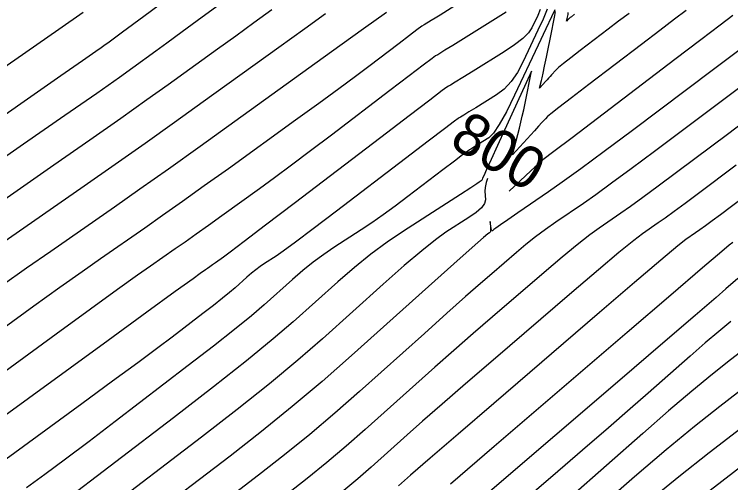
# Model space of a CAD drawing. Extents: x 2079879 to 2092887, y 778083 to 784051.
# Drawn here: x 2083989.89 to 2084037.6, y 780813.21 to 780844.44 of the extents above; entities that cross this region are included whole.
import ezdxf

# ---------------------------------------------------------------- set-up
doc = ezdxf.new("R2010")
doc.units = 0
doc.layers.add('DT_X_Contour_Major', color=7, linetype='Continuous')
doc.layers.add('DT_X_Contour_Minor', color=7, linetype='Continuous')

msp = doc.modelspace()

# ---------------------------------------------------------------- linework, layer by layer
at = {"layer": 'DT_X_Contour_Major'}
for points in [[(2084010.72, 780850.406), (2084010.313, 780850.113), (2084008.721, 780848.939), (2084004.016, 780845.443), (2084002.4, 780844.244), (2084001.079, 780843.267), (2084000.055, 780842.513), (2083999.326, 780841.983), (2083997.776, 780840.865), (2083996.886, 780840.232), (2083995.377, 780839.173), (2083993.25, 780837.687), (2083990.504, 780835.775), (2083982.357, 780830.105)], [(2084022.658, 780844.588), (2084021.945, 780844.143), (2084019.804, 780842.811), (2084019.095, 780842.37), (2084018.573, 780842.046), (2084018.238, 780841.839), (2084018.089, 780841.749), (2084017.943, 780841.664), (2084017.713, 780841.497), (2084017.13, 780841.059), (2084016.196, 780840.35), (2084014.911, 780839.37), (2084011.013, 780836.395), (2084009.617, 780835.335), (2084008.352, 780834.384), (2084007.218, 780833.544), (2084006.216, 780832.813), (2084003.717, 780831.011), (2084002.82, 780830.366), (2084002.003, 780829.782), (2084001.266, 780829.26), (2084000.608, 780828.799), (2083998.96, 780827.652), (2083998.103, 780827.046), (2083996.77, 780826.088), (2083994.96, 780824.777), (2083992.674, 780823.114), (2083985.941, 780818.21)], [(2084037.749, 780844.363), (2084036.898, 780843.714), (2084035.614, 780842.736), (2084033.895, 780841.427), (2084028.733, 780837.497), (2084027.039, 780836.207), (2084025.828, 780835.286), (2084025.102, 780834.733), (2084024.859, 780834.548), (2084024.856, 780834.545), (2084024.854, 780834.542), (2084024.849, 780834.537), (2084024.842, 780834.529), (2084024.832, 780834.518), (2084024.803, 780834.486), (2084024.792, 780834.475), (2084024.784, 780834.466), (2084024.778, 780834.458), (2084024.773, 780834.454), (2084024.764, 780834.443), (2084024.709, 780834.391), (2084024.552, 780834.245), (2084024.292, 780834.003), (2084023.931, 780833.667), (2084022.849, 780832.66)], [(2084021.416, 780833.499), (2084021.319, 780833.219), (2084021.246, 780832.901), (2084021.232, 780832.649), (2084021.271, 780832.063), (2084021.213, 780831.824), (2084021.008, 780831.549), (2084020.657, 780831.236), (2084020.16, 780830.887), (2084018.638, 780829.906), (2084017.949, 780829.413), (2084017.023, 780828.673), (2084015.86, 780827.683), (2084014.46, 780826.446), (2084010.41, 780822.814), (2084008.768, 780821.382), (2084006.878, 780819.811), (2084004.742, 780818.101), (2084002.358, 780816.251), (2083995.671, 780811.132)], [(2084038.477, 780832.249), (2084036.921, 780831.081), (2084036.381, 780830.676), (2084035.925, 780830.34), (2084035.555, 780830.072), (2084035.271, 780829.872), (2084034.625, 780829.43), (2084034.084, 780829.002), (2084032.942, 780828.046), (2084031.201, 780826.565), (2084028.861, 780824.558), (2084021.819, 780818.503), (2084019.443, 780816.457), (2084017.593, 780814.859), (2084016.272, 780813.711), (2084015.478, 780813.011)], [(2084041.095, 780821.553), (2084036.888, 780818.301), (2084035.204, 780816.965), (2084033.305, 780815.397), (2084031.193, 780813.597), (2084028.867, 780811.564), (2084022.378, 780805.834), (2084020.224, 780803.935), (2084018.628, 780802.537), (2084017.589, 780801.64), (2084017.108, 780801.244), (2084016.571, 780800.854), (2084016.195, 780800.587), (2084015.472, 780800.077), (2084014.401, 780799.326), (2084012.982, 780798.332), (2084008.735, 780795.359), (2084007.243, 780794.315), (2084005.952, 780793.414), (2084004.863, 780792.656), (2084003.975, 780792.04), (2084002.509, 780791.027)]]:
    msp.add_lwpolyline(points, dxfattribs=at)
at = {"layer": 'DT_X_Contour_Minor'}
for points in [[(2084000.474, 780845.757), (2083998.512, 780844.299), (2083997.089, 780843.244), (2083996.206, 780842.591), (2083995.863, 780842.34), (2083995.666, 780842.208), (2083995.319, 780841.967), (2083994.423, 780841.343), (2083992.98, 780840.335), (2083990.99, 780838.944), (2083984.951, 780834.725)], [(2084019.237, 780845.009), (2084018.248, 780844.394), (2084017.915, 780844.188), (2084017.658, 780844.029), (2084017.476, 780843.917), (2084017.37, 780843.854), (2084017.188, 780843.748), (2084017.033, 780843.641), (2084016.704, 780843.398), (2084016.202, 780843.02), (2084015.527, 780842.506), (2084013.494, 780840.955), (2084012.617, 780840.294), (2084011.512, 780839.478), (2084010.179, 780838.504), (2084008.618, 780837.374), (2084004.149, 780834.15), (2084002.545, 780832.996), (2084001.083, 780831.952), (2083999.764, 780831.018), (2083998.587, 780830.194), (2083995.639, 780828.143), (2083994.408, 780827.278), (2083992.927, 780826.221), (2083991.194, 780824.973), (2083989.211, 780823.533)], [(2084007.035, 780844.744), (2084005.848, 780843.873), (2084004.643, 780842.994), (2084003.419, 780842.107), (2084000.128, 780839.733), (2083998.727, 780838.731), (2083996.993, 780837.505), (2083994.926, 780836.054), (2083992.525, 780834.38), (2083985.678, 780829.615)], [(2083994.476, 780844.558), (2083992.856, 780843.439), (2083990.651, 780841.906), (2083987.861, 780839.959)], [(2084024.912, 780844.754), (2084024.757, 780844.37), (2084024.364, 780843.537), (2084024.138, 780843.204), (2084023.754, 780842.827), (2084023.214, 780842.408), (2084022.516, 780841.946), (2084020.444, 780840.658), (2084019.76, 780840.232), (2084019.259, 780839.921), (2084018.942, 780839.725), (2084018.809, 780839.644), (2084018.699, 780839.58), (2084018.393, 780839.353), (2084017.557, 780838.72), (2084016.191, 780837.68), (2084014.295, 780836.234), (2084008.532, 780831.836), (2084006.616, 780830.375), (2084005.191, 780829.291), (2084004.257, 780828.583), (2084003.814, 780828.252), (2084003.286, 780827.871), (2084003.096, 780827.735), (2084002.923, 780827.612), (2084002.767, 780827.501), (2084002.628, 780827.404), (2084002.28, 780827.161), (2084001.798, 780826.814), (2084000.614, 780825.954), (2083998.726, 780824.581), (2083996.136, 780822.695), (2083988.293, 780816.982)], [(2084025.378, 780844.774), (2084025.107, 780844.117), (2084024.771, 780843.376), (2084023.787, 780841.291), (2084023.4, 780840.566), (2084022.974, 780839.956), (2084022.511, 780839.461), (2084022.01, 780839.08), (2084020.623, 780838.217), (2084020.165, 780837.932), (2084019.829, 780837.724), (2084019.617, 780837.593), (2084019.528, 780837.538), (2084019.454, 780837.496), (2084019.215, 780837.317), (2084018.55, 780836.814), (2084017.462, 780835.985), (2084015.949, 780834.831), (2084011.349, 780831.32), (2084009.803, 780830.145), (2084008.617, 780829.252), (2084007.79, 780828.643), (2084007.323, 780828.316), (2084006.556, 780827.821), (2084006.267, 780827.625), (2084005.975, 780827.409), (2084005.681, 780827.172), (2084005.384, 780826.915), (2084004.59, 780826.203), (2084004.233, 780825.896), (2084003.758, 780825.507), (2084003.164, 780825.038), (2084002.452, 780824.488), (2084000.397, 780822.915), (2083999.442, 780822.194), (2083998.121, 780821.214), (2083996.433, 780819.974), (2083994.377, 780818.473), (2083988.407, 780814.125)], [(2084010.618, 780844.478), (2084009.231, 780843.474), (2084007.511, 780842.231), (2084002.48, 780838.602), (2084000.569, 780837.23), (2083998.609, 780835.836), (2083996.601, 780834.421), (2083994.545, 780832.984), (2083988.998, 780829.124)], [(2084014.673, 780844.571), (2084013.14, 780843.464), (2084011.02, 780841.934), (2084004.581, 780837.29), (2084002.269, 780835.627), (2084000.163, 780834.123), (2083998.262, 780832.777), (2083996.566, 780831.589), (2083992.319, 780828.633), (2083990.713, 780827.51), (2083989.083, 780826.355)], [(2084025.895, 780844.741), (2084025.672, 780844.265), (2084025.302, 780843.479), (2084024.785, 780842.382), (2084023.211, 780839.045), (2084022.662, 780837.929), (2084022.194, 780837.085), (2084021.808, 780836.514), (2084021.504, 780836.214), (2084020.802, 780835.777), (2084020.57, 780835.632), (2084020.4, 780835.527), (2084020.292, 780835.461), (2084020.247, 780835.433), (2084020.21, 780835.411), (2084020.088, 780835.321), (2084019.752, 780835.066), (2084019.201, 780834.646), (2084018.435, 780834.062), (2084016.105, 780832.284), (2084015.255, 780831.646), (2084014.454, 780831.064), (2084013.701, 780830.54), (2084012.996, 780830.072), (2084011.181, 780828.901), (2084010.497, 780828.438), (2084009.807, 780827.927), (2084009.111, 780827.367), (2084008.41, 780826.759), (2084006.53, 780825.073), (2084005.685, 780824.346), (2084004.561, 780823.427), (2084003.156, 780822.317), (2084001.472, 780821.016), (2083996.608, 780817.293), (2083994.871, 780815.968), (2083993.308, 780814.788), (2083991.92, 780813.751), (2083990.707, 780812.859)], [(2084034.638, 780844.702), (2084033.866, 780844.111), (2084032.876, 780843.355), (2084031.667, 780842.434), (2084028.153, 780839.759), (2084026.993, 780838.874), (2084026.149, 780838.225), (2084025.622, 780837.812), (2084025.41, 780837.635), (2084025.267, 780837.478), (2084025.03, 780837.218), (2084024.814, 780836.98), (2084024.532, 780836.671), (2084023.066, 780835.062), (2084023.531, 780836.848), (2084023.63, 780837.24), (2084023.726, 780837.649), (2084023.821, 780838.077), (2084023.914, 780838.522), (2084024.343, 780840.644), (2084022.083, 780835.695), (2084021.657, 780834.763), (2084021.349, 780834.088), (2084021.158, 780833.67), (2084021.084, 780833.509), (2084021.042, 780833.421), (2084021.028, 780833.392), (2084021.016, 780833.37), (2084021.006, 780833.355), (2084020.998, 780833.348), (2084020.98, 780833.336), (2084020.974, 780833.333), (2084020.97, 780833.33), (2084020.966, 780833.328), (2084020.965, 780833.327), (2084020.962, 780833.325), (2084020.954, 780833.318), (2084020.94, 780833.308), (2084020.92, 780833.293), (2084020.861, 780833.248), (2084020.708, 780833.147), (2084020.291, 780832.876), (2084019.612, 780832.437), (2084018.669, 780831.829), (2084015.806, 780829.982), (2084014.727, 780829.251), (2084013.639, 780828.444), (2084012.542, 780827.561), (2084011.435, 780826.602), (2084008.47, 780823.944), (2084007.138, 780822.796), (2084005.364, 780821.347), (2084003.149, 780819.596), (2084000.492, 780817.544), (2083992.819, 780811.67)], [(2084030.833, 780844.507), (2084030.137, 780843.974), (2084029.438, 780843.441), (2084027.573, 780842.021), (2084026.947, 780841.54), (2084026.47, 780841.163), (2084026.141, 780840.891), (2084025.961, 780840.723), (2084025.678, 780840.412), (2084025.574, 780840.298), (2084025.475, 780840.189), (2084025.379, 780840.084), (2084025.288, 780839.984), (2084024.872, 780839.527), (2084025.004, 780840.034), (2084025.045, 780840.212), (2084025.113, 780840.528), (2084025.208, 780840.983), (2084025.328, 780841.577), (2084025.686, 780843.345), (2084025.804, 780843.929), (2084025.89, 780844.355), (2084025.944, 780844.623)], [(2084027.21, 780844.448), (2084026.993, 780844.282), (2084026.918, 780844.225), (2084026.859, 780844.177), (2084026.814, 780844.138), (2084026.784, 780844.108), (2084026.678, 780843.992), (2084026.77, 780844.428), (2084026.776, 780844.554)], [(2084038.246, 780842.097), (2084036.464, 780840.758), (2084031.055, 780836.694), (2084029.185, 780835.296), (2084027.63, 780834.147), (2084026.391, 780833.248), (2084025.468, 780832.598), (2084023.428, 780831.201), (2084022.754, 780830.738), (2084022.264, 780830.399), (2084021.956, 780830.183), (2084021.832, 780830.091), (2084021.744, 780830.009), (2084021.713, 780829.995), (2084021.687, 780830.014), (2084021.665, 780830.065), (2084021.648, 780830.15), (2084021.578, 780830.621), (2084021.61, 780830.137), (2084021.611, 780830.042), (2084021.599, 780829.967), (2084021.575, 780829.911), (2084021.538, 780829.873), (2084021.423, 780829.799), (2084021.144, 780829.558), (2084020.395, 780828.893), (2084019.175, 780827.804), (2084017.485, 780826.289), (2084012.35, 780821.684), (2084010.4, 780819.97), (2084008.402, 780818.283), (2084006.356, 780816.621), (2084004.261, 780814.986), (2083998.61, 780810.66)], [(2084038.471, 780839.763), (2084036.967, 780838.631), (2084032.522, 780835.291), (2084030.977, 780834.136), (2084029.675, 780833.175), (2084028.618, 780832.41), (2084027.805, 780831.839), (2084025.961, 780830.575), (2084025.278, 780830.094), (2084024.614, 780829.599), (2084023.968, 780829.089), (2084023.34, 780828.564), (2084021.69, 780827.145), (2084020.946, 780826.498), (2084019.95, 780825.619), (2084018.703, 780824.509), (2084017.205, 780823.168), (2084012.874, 780819.284), (2084011.236, 780817.844), (2084009.572, 780816.437), (2084007.881, 780815.062), (2084006.164, 780813.721), (2084001.55, 780810.189)], [(2084038.697, 780837.429), (2084037.471, 780836.504), (2084033.988, 780833.888), (2084032.778, 780832.983), (2084031.759, 780832.23), (2084030.931, 780831.631), (2084030.293, 780831.183), (2084028.849, 780830.194), (2084028.213, 780829.73), (2084027.39, 780829.081), (2084026.379, 780828.248), (2084025.18, 780827.229), (2084021.733, 780824.265), (2084020.445, 780823.151), (2084019.165, 780822.033), (2084017.893, 780820.91), (2084016.629, 780819.782), (2084013.27, 780816.77), (2084012, 780815.653), (2084010.71, 780814.562), (2084009.399, 780813.497), (2084008.067, 780812.456)], [(2084037.974, 780834.377), (2084035.455, 780832.484), (2084034.579, 780831.83), (2084033.842, 780831.285), (2084033.243, 780830.851), (2084032.782, 780830.528), (2084031.737, 780829.812), (2084031.148, 780829.366), (2084030.166, 780828.564), (2084028.79, 780827.406), (2084027.02, 780825.893), (2084021.776, 780821.384), (2084019.944, 780819.804), (2084018.379, 780818.446), (2084017.082, 780817.31), (2084016.054, 780816.397), (2084013.667, 780814.257), (2084012.765, 780813.463), (2084011.848, 780812.688)], [(2084037.759, 780829.217), (2084037.514, 780829.049), (2084037.019, 780828.637), (2084035.718, 780827.529), (2084033.612, 780825.724), (2084030.701, 780823.222), (2084021.862, 780815.622), (2084018.941, 780813.11)], [(2084038.073, 780826.824), (2084037.292, 780826.134), (2084036.63, 780825.56), (2084035.23, 780824.356), (2084033.093, 780822.52), (2084030.217, 780820.053), (2084021.564, 780812.633)], [(2084037.611, 780823.96), (2084036.813, 780823.299), (2084035.912, 780822.531), (2084034.91, 780821.655), (2084032.102, 780819.175), (2084030.916, 780818.134), (2084029.463, 780816.871), (2084027.744, 780815.387), (2084025.758, 780813.68), (2084020.106, 780808.834)], [(2084040.562, 780823.698), (2084037.598, 780821.407), (2084036.399, 780820.455), (2084035.024, 780819.317), (2084033.474, 780817.994), (2084031.748, 780816.485), (2084026.913, 780812.215)], [(2084041.628, 780819.408), (2084036.179, 780815.195), (2084034.141, 780813.593), (2084032.117, 780811.945)], [(2084042.161, 780817.263), (2084035.469, 780812.089)]]:
    msp.add_lwpolyline(points, dxfattribs=at)

# ---------------------------------------------------------------- texts
at = {"layer": 'DT_X_Contour_Major'}
msp.add_text('800', height=2.8, rotation=329.6626, dxfattribs=at).set_placement((2084018.764, 780835.71))

doc.saveas('drawing.dxf')
